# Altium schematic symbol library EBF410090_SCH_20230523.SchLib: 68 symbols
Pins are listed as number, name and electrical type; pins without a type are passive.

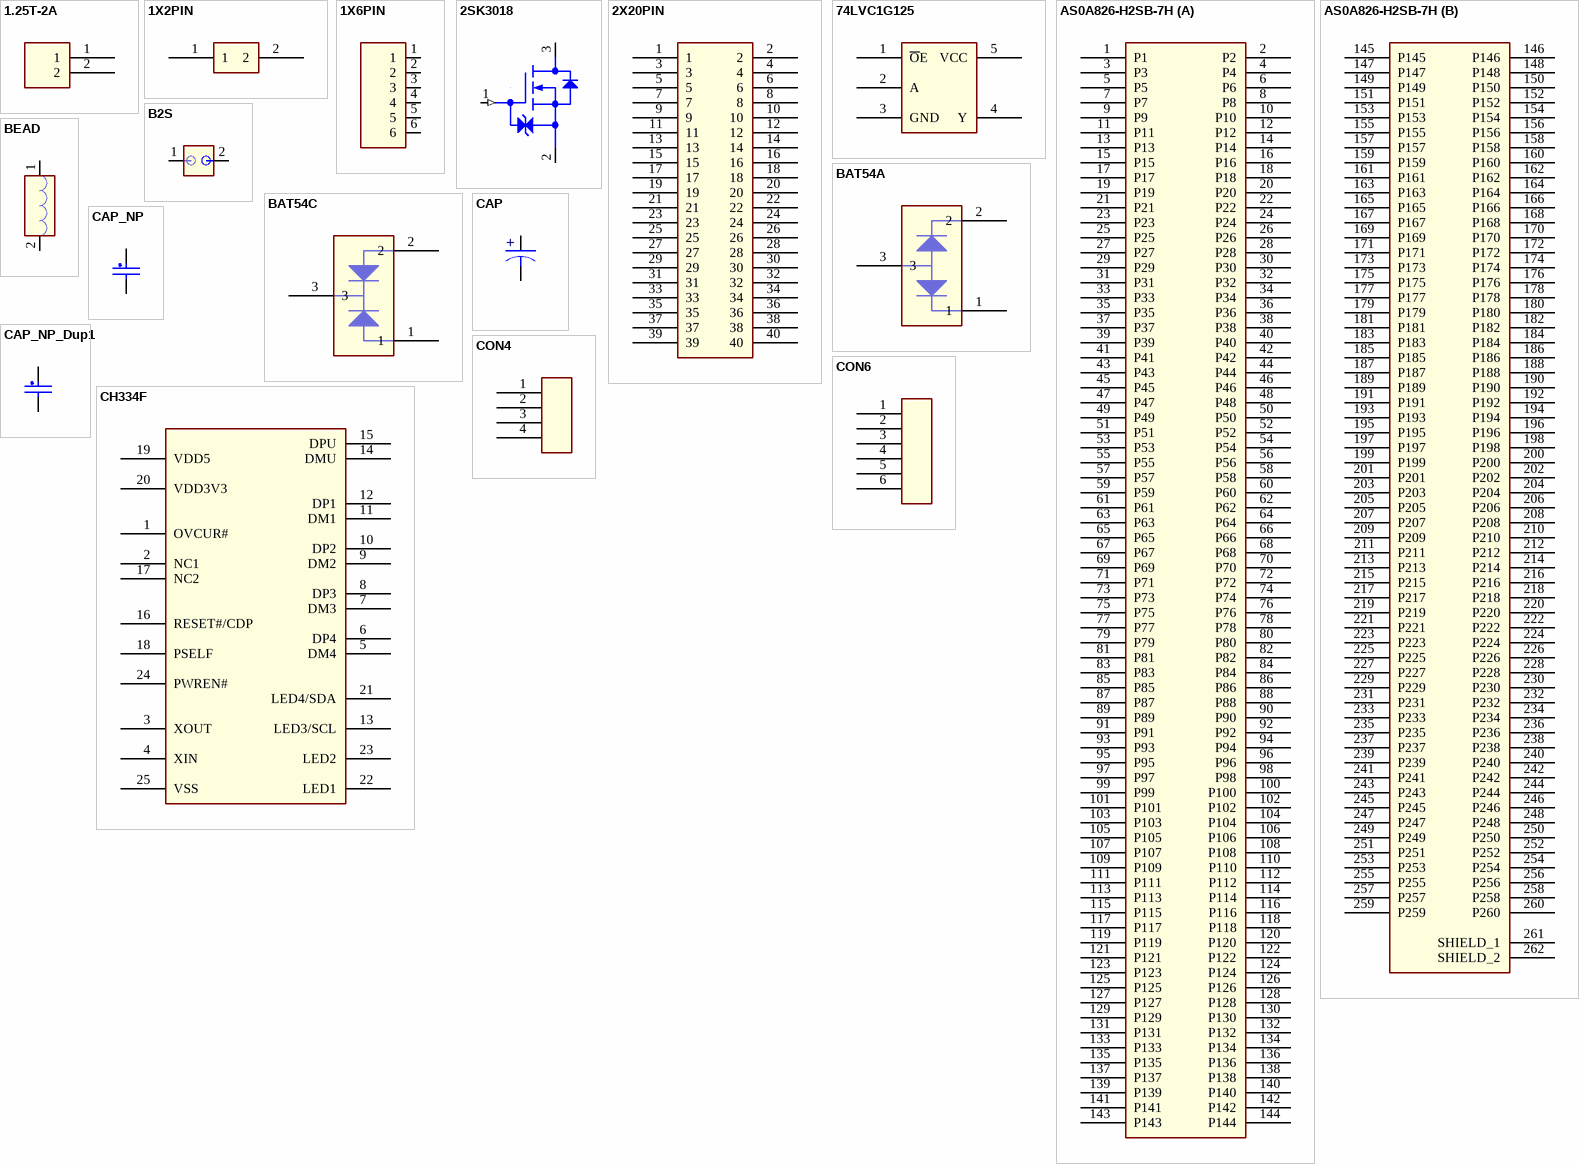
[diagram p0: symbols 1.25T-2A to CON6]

## 1.25T-2A
designator J?
footprint gh1p25_th_2p
pins: 1, 2

## 1X2PIN
designator J?
pins: 1, 2

## 1X6PIN
designator J?
pins: 1, 2, 3, 4, 5, 6

## 2SK3018
designator Q?
CLASS: IC
pins: 1 GATE (in), 2 SOURCE, 3 DRAIN

## 2X20PIN
designator J?
pins: 1, 2, 3, 4, 5, 6, 7, 8, 9, 10, 11, 12, 13, 14, 15, 16, 17, 18, 19, 20, 21, 22, 23, 24, 25, 26, 27, 28, 29, 30, 31, 32, 33, 34, 35, 36, 37, 38, 39, 40

## 74LVC1G125
designator U?
footprint SOT-353
pins: 1 ~{O}E, 2 A, 3 GND, 4 Y, 5 VCC

## AS0A826-H2SB-7H
designator J?
part A pins: 1 P1, 2 P2, 3 P3, 4 P4, 5 P5, 6 P6, 7 P7, 8 P8, 9 P9, 10 P10, 11 P11, 12 P12, 13 P13, 14 P14, 15 P15, 16 P16, 17 P17, 18 P18, 19 P19, 20 P20, 21 P21, 22 P22, 23 P23, 24 P24, 25 P25, 26 P26, 27 P27, 28 P28, 29 P29, 30 P30, 31 P31, 32 P32, 33 P33, 34 P34, 35 P35, 36 P36, 37 P37, 38 P38, 39 P39, 40 P40, 41 P41, 42 P42, 43 P43, 44 P44, 45 P45, 46 P46, 47 P47, 48 P48, 49 P49, 50 P50, 51 P51, 52 P52, 53 P53, 54 P54, 55 P55, 56 P56, 57 P57, 58 P58, 59 P59, 60 P60, 61 P61, 62 P62, 63 P63, 64 P64, 65 P65, 66 P66, 67 P67, 68 P68, 69 P69, 70 P70, 71 P71, 72 P72, 73 P73, 74 P74, 75 P75, 76 P76, 77 P77, 78 P78, 79 P79, 80 P80, 81 P81, 82 P82, 83 P83, 84 P84, 85 P85, 86 P86, 87 P87, 88 P88, 89 P89, 90 P90, 91 P91, 92 P92, 93 P93, 94 P94, 95 P95, 96 P96, 97 P97, 98 P98, 99 P99, 100 P100, 101 P101, 102 P102, 103 P103, 104 P104, 105 P105, 106 P106, 107 P107, 108 P108, 109 P109, 110 P110, 111 P111, 112 P112, 113 P113, 114 P114, 115 P115, 116 P116, 117 P117, 118 P118, 119 P119, 120 P120, 121 P121, 122 P122, 123 P123, 124 P124, 125 P125, 126 P126, 127 P127, 128 P128, 129 P129, 130 P130, 131 P131, 132 P132, 133 P133, 134 P134, 135 P135, 136 P136, 137 P137, 138 P138, 139 P139, 140 P140, 141 P141, 142 P142, 143 P143, 144 P144
part B pins: 145 P145, 146 P146, 147 P147, 148 P148, 149 P149, 150 P150, 151 P151, 152 P152, 153 P153, 154 P154, 155 P155, 156 P156, 157 P157, 158 P158, 159 P159, 160 P160, 161 P161, 162 P162, 163 P163, 164 P164, 165 P165, 166 P166, 167 P167, 168 P168, 169 P169, 170 P170, 171 P171, 172 P172, 173 P173, 174 P174, 175 P175, 176 P176, 177 P177, 178 P178, 179 P179, 180 P180, 181 P181, 182 P182, 183 P183, 184 P184, 185 P185, 186 P186, 187 P187, 188 P188, 189 P189, 190 P190, 191 P191, 192 P192, 193 P193, 194 P194, 195 P195, 196 P196, 197 P197, 198 P198, 199 P199, 200 P200, 201 P201, 202 P202, 203 P203, 204 P204, 205 P205, 206 P206, 207 P207, 208 P208, 209 P209, 210 P210, 211 P211, 212 P212, 213 P213, 214 P214, 215 P215, 216 P216, 217 P217, 218 P218, 219 P219, 220 P220, 221 P221, 222 P222, 223 P223, 224 P224, 225 P225, 226 P226, 227 P227, 228 P228, 229 P229, 230 P230, 231 P231, 232 P232, 233 P233, 234 P234, 235 P235, 236 P236, 237 P237, 238 P238, 239 P239, 240 P240, 241 P241, 242 P242, 243 P243, 244 P244, 245 P245, 246 P246, 247 P247, 248 P248, 249 P249, 250 P250, 251 P251, 252 P252, 253 P253, 254 P254, 255 P255, 256 P256, 257 P257, 258 P258, 259 P259, 260 P260, 261 SHIELD_1, 262 SHIELD_2

## B2S
designator J?
pins: 1, 2

## BAT54A
designator D?
footprint SOT23
pins: 1, 2, 3

## BAT54C
designator D?
footprint SOT23
pins: 1, 2, 3

## BEAD
designator L?
CLASS: DISCRETE
pins: 1, 2

## CAP
designator C?
footprint T2012
pins: 1, 2

## CAP_NP
designator C?
CLASS: DISCRETE
pins: 1, 2

## CAP_NP_Dup1
designator C?
CLASS: DISCRETE
pins: 1, 2

## CH334F
designator U?
pins: 1 OVCUR#, 2 NC1, 3 XOUT, 4 XIN, 5 DM4, 6 DP4, 7 DM3, 8 DP3, 9 DM2, 10 DP2, 11 DM1, 12 DP1, 13 LED3/SCL, 14 DMU, 15 DPU, 16 RESET#/CDP, 17 NC2, 18 PSELF, 19 VDD5, 20 VDD3V3, 21 LED4/SDA, 22 LED1, 23 LED2, 24 PWREN#, 25 VSS

## CON4
designator J?
pins: 1, 2, 3, 4

## CON6
designator J?
pins: 1, 2, 3, 4, 5, 6

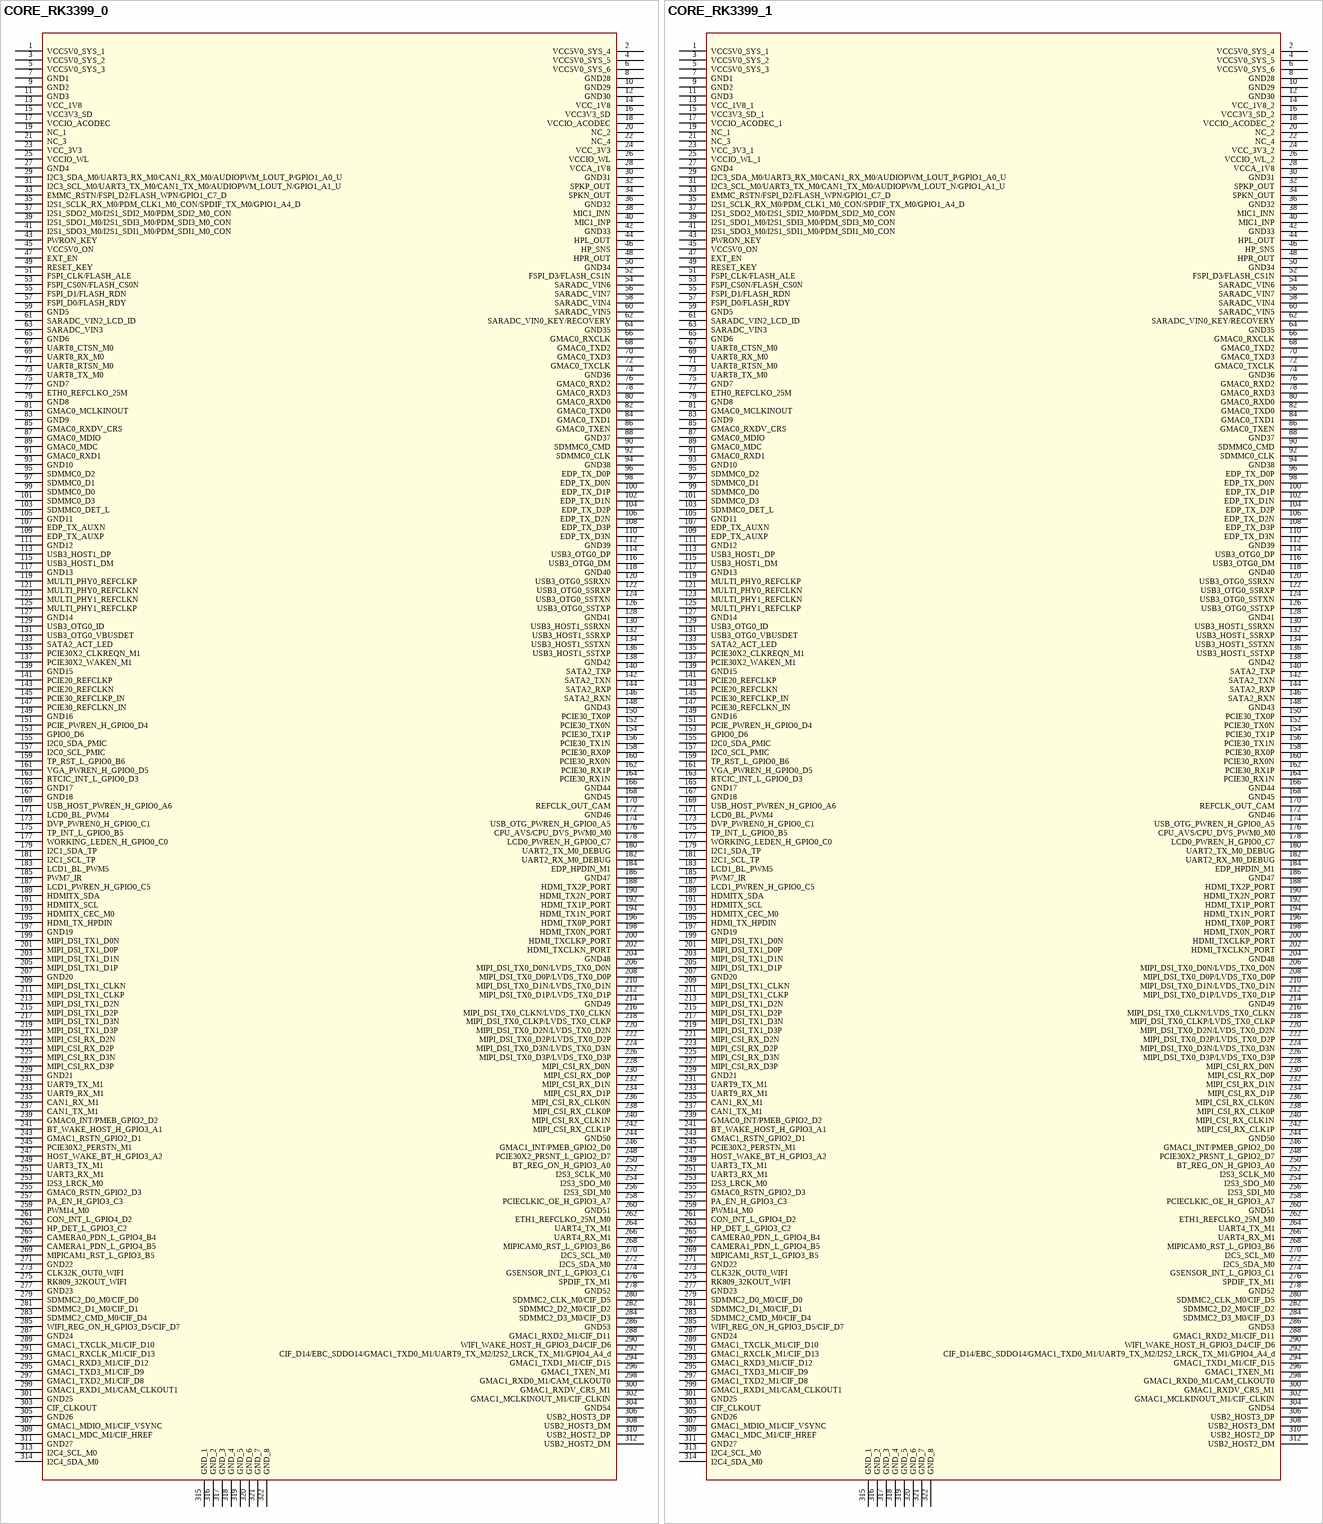
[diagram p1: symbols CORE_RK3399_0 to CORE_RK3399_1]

## CORE_RK3399_0
designator U?
pins: 1 VCC5V0_SYS_1, 2 VCC5V0_SYS_4, 3 VCC5V0_SYS_2, 4 VCC5V0_SYS_5, 5 VCC5V0_SYS_3, 6 VCC5V0_SYS_6, 7 GND1, 8 GND28, 9 GND2, 10 GND29, 11 GND3, 12 GND30, 13 VCC_1V8, 14 VCC_1V8, 15 VCC3V3_SD, 16 VCC3V3_SD, 17 VCCIO_ACODEC, 18 VCCIO_ACODEC, 19 NC_1, 20 NC_2, 21 NC_3, 22 NC_4, 23 VCC_3V3, 24 VCC_3V3, 25 VCCIO_WL, 26 VCCIO_WL, 27 GND4, 28 VCCA_1V8, 29 I2C3_SDA_M0/UART3_RX_M0/CAN1_RX_M0/AUDIOPWM_LOUT_P/GPIO1_A0_U, 30 GND31, 31 I2C3_SCL_M0/UART3_TX_M0/CAN1_TX_M0/AUDIOPWM_LOUT_N/GPIO1_A1_U, 32 SPKP_OUT, 33 EMMC_RSTN/FSPI_D2/FLASH_WPN/GPIO1_C7_D, 34 SPKN_OUT, 35 I2S1_SCLK_RX_M0/PDM_CLK1_M0_CON/SPDIF_TX_M0/GPIO1_A4_D, 36 GND32, 37 I2S1_SDO2_M0/I2S1_SDI2_M0/PDM_SDI2_M0_CON, 38 MIC1_INN, 39 I2S1_SDO1_M0/I2S1_SDI3_M0/PDM_SDI3_M0_CON, 40 MIC1_INP, 41 I2S1_SDO3_M0/I2S1_SDI1_M0/PDM_SDI1_M0_CON, 42 GND33, 43 PWRON_KEY, 44 HPL_OUT, 45 VCC5V0_ON, 46 HP_SNS, 47 EXT_EN, 48 HPR_OUT, 49 RESET_KEY, 50 GND34, 51 FSPI_CLK/FLASH_ALE, 52 FSPI_D3/FLASH_CS1N, 53 FSPI_CS0N/FLASH_CS0N, 54 SARADC_VIN6, 55 FSPI_D1/FLASH_RDN, 56 SARADC_VIN7, 57 FSPI_D0/FLASH_RDY, 58 SARADC_VIN4, 59 GND5, 60 SARADC_VIN5, 61 SARADC_VIN2_LCD_ID, 62 SARADC_VIN0_KEY/RECOVERY, 63 SARADC_VIN3, 64 GND35, 65 GND6, 66 GMAC0_RXCLK, 67 UART8_CTSN_M0, 68 GMAC0_TXD2, 69 UART8_RX_M0, 70 GMAC0_TXD3, 71 UART8_RTSN_M0, 72 GMAC0_TXCLK, 73 UART8_TX_M0, 74 GND36, 75 GND7, 76 GMAC0_RXD2, 77 ETH0_REFCLKO_25M, 78 GMAC0_RXD3, 79 GND8, 80 GMAC0_RXD0, 81 GMAC0_MCLKINOUT, 82 GMAC0_TXD0, 83 GND9, 84 GMAC0_TXD1, 85 GMAC0_RXDV_CRS, 86 GMAC0_TXEN, 87 GMAC0_MDIO, 88 GND37, 89 GMAC0_MDC, 90 SDMMC0_CMD, 91 GMAC0_RXD1, 92 SDMMC0_CLK, 93 GND10, 94 GND38, 95 SDMMC0_D2, 96 EDP_TX_D0P, 97 SDMMC0_D1, 98 EDP_TX_D0N, 99 SDMMC0_D0, 100 EDP_TX_D1P, 101 SDMMC0_D3, 102 EDP_TX_D1N, 103 SDMMC0_DET_L, 104 EDP_TX_D2P, 105 GND11, 106 EDP_TX_D2N, 107 EDP_TX_AUXN, 108 EDP_TX_D3P, 109 EDP_TX_AUXP, 110 EDP_TX_D3N, 111 GND12, 112 GND39, 113 USB3_HOST1_DP, 114 USB3_OTG0_DP, 115 USB3_HOST1_DM, 116 USB3_OTG0_DM, 117 GND13, 118 GND40, 119 MULTI_PHY0_REFCLKP, 120 USB3_OTG0_SSRXN, 121 MULTI_PHY0_REFCLKN, 122 USB3_OTG0_SSRXP, 123 MULTI_PHY1_REFCLKN, 124 USB3_OTG0_SSTXN, 125 MULTI_PHY1_REFCLKP, 126 USB3_OTG0_SSTXP, 127 GND14, 128 GND41, 129 USB3_OTG0_ID, 130 USB3_HOST1_SSRXN, 131 USB3_OTG0_VBUSDET, 132 USB3_HOST1_SSRXP, 133 SATA2_ACT_LED, 134 USB3_HOST1_SSTXN, 135 PCIE30X2_CLKREQN_M1, 136 USB3_HOST1_SSTXP, 137 PCIE30X2_WAKEN_M1, 138 GND42, 139 GND15, 140 SATA2_TXP, 141 PCIE20_REFCLKP, 142 SATA2_TXN, 143 PCIE20_REFCLKN, 144 SATA2_RXP, 145 PCIE30_REFCLKP_IN, 146 SATA2_RXN, 147 PCIE30_REFCLKN_IN, 148 GND43, 149 GND16, 150 PCIE30_TX0P, 151 PCIE_PWREN_H_GPIO0_D4, 152 PCIE30_TX0N, 153 GPIO0_D6, 154 PCIE30_TX1P, 155 I2C0_SDA_PMIC, 156 PCIE30_TX1N, 157 I2C0_SCL_PMIC, 158 PCIE30_RX0P, 159 TP_RST_L_GPIO0_B6, 160 PCIE30_RX0N, 161 VGA_PWREN_H_GPIO0_D5, 162 PCIE30_RX1P, 163 RTCIC_INT_L_GPIO0_D3, 164 PCIE30_RX1N, 165 GND17, 166 GND44, 167 GND18, 168 GND45, 169 USB_HOST_PWREN_H_GPIO0_A6, 170 REFCLK_OUT_CAM, 171 LCD0_BL_PWM4, 172 GND46, 173 DVP_PWREN0_H_GPIO0_C1, 174 USB_OTG_PWREN_H_GPIO0_A5, 175 TP_INT_L_GPIO0_B5, 176 CPU_AVS/CPU_DVS_PWM0_M0, 177 WORKING_LEDEN_H_GPIO0_C0, 178 LCD0_PWREN_H_GPIO0_C7, 179 I2C1_SDA_TP, 180 UART2_TX_M0_DEBUG, 181 I2C1_SCL_TP, 182 UART2_RX_M0_DEBUG, 183 LCD1_BL_PWM5, 184 EDP_HPDIN_M1, 185 PWM7_IR, 186 GND47, 187 LCD1_PWREN_H_GPIO0_C5, 188 HDMI_TX2P_PORT, 189 HDMITX_SDA, 190 HDMI_TX2N_PORT, 191 HDMITX_SCL, 192 HDMI_TX1P_PORT, 193 HDMITX_CEC_M0, 194 HDMI_TX1N_PORT, 195 HDMI_TX_HPDIN, 196 HDMI_TX0P_PORT, 197 GND19, 198 HDMI_TX0N_PORT, 199 MIPI_DSI_TX1_D0N, 200 HDMI_TXCLKP_PORT, 201 MIPI_DSI_TX1_D0P, 202 HDMI_TXCLKN_PORT, 203 MIPI_DSI_TX1_D1N, 204 GND48, 205 MIPI_DSI_TX1_D1P, 206 MIPI_DSI_TX0_D0N/LVDS_TX0_D0N, 207 GND20, 208 MIPI_DSI_TX0_D0P/LVDS_TX0_D0P, 209 MIPI_DSI_TX1_CLKN, 210 MIPI_DSI_TX0_D1N/LVDS_TX0_D1N, 211 MIPI_DSI_TX1_CLKP, 212 MIPI_DSI_TX0_D1P/LVDS_TX0_D1P, 213 MIPI_DSI_TX1_D2N, 214 GND49, 215 MIPI_DSI_TX1_D2P, 216 MIPI_DSI_TX0_CLKN/LVDS_TX0_CLKN, 217 MIPI_DSI_TX1_D3N, 218 MIPI_DSI_TX0_CLKP/LVDS_TX0_CLKP, 219 MIPI_DSI_TX1_D3P, 220 MIPI_DSI_TX0_D2N/LVDS_TX0_D2N, 221 MIPI_CSI_RX_D2N, 222 MIPI_DSI_TX0_D2P/LVDS_TX0_D2P, 223 MIPI_CSI_RX_D2P, 224 MIPI_DSI_TX0_D3N/LVDS_TX0_D3N, 225 MIPI_CSI_RX_D3N, 226 MIPI_DSI_TX0_D3P/LVDS_TX0_D3P, 227 MIPI_CSI_RX_D3P, 228 MIPI_CSI_RX_D0N, 229 GND21, 230 MIPI_CSI_RX_D0P, 231 UART9_TX_M1, 232 MIPI_CSI_RX_D1N, 233 UART9_RX_M1, 234 MIPI_CSI_RX_D1P, 235 CAN1_RX_M1, 236 MIPI_CSI_RX_CLK0N, 237 CAN1_TX_M1, 238 MIPI_CSI_RX_CLK0P, 239 GMAC0_INT/PMEB_GPIO2_D2, 240 MIPI_CSI_RX_CLK1N, 241 BT_WAKE_HOST_H_GPIO3_A1, 242 MIPI_CSI_RX_CLK1P, 243 GMAC1_RSTN_GPIO2_D1, 244 GND50, 245 PCIE30X2_PERSTN_M1, 246 GMAC1_INT/PMEB_GPIO2_D0, 247 HOST_WAKE_BT_H_GPIO3_A2, 248 PCIE30X2_PRSNT_L_GPIO2_D7, 249 UART3_TX_M1, 250 BT_REG_ON_H_GPIO3_A0, 251 UART3_RX_M1, 252 I2S3_SCLK_M0, 253 I2S3_LRCK_M0, 254 I2S3_SDO_M0, 255 GMAC0_RSTN_GPIO2_D3, 256 I2S3_SDI_M0, 257 PA_EN_H_GPIO3_C3, 258 PCIECLKIC_OE_H_GPIO3_A7, 259 PWM14_M0, 260 GND51, 261 CON_INT_L_GPIO4_D2, 262 ETH1_REFCLKO_25M_M0, 263 HP_DET_L_GPIO3_C2, 264 UART4_TX_M1, 265 CAMERA0_PDN_L_GPIO4_B4, 266 UART4_RX_M1, 267 CAMERA1_PDN_L_GPIO4_B5, 268 MIPICAM0_RST_L_GPIO3_B6, 269 MIPICAM1_RST_L_GPIO3_B5, 270 I2C5_SCL_M0, 271 GND22, 272 I2C5_SDA_M0, 273 CLK32K_OUT0_WIFI, 274 GSENSOR_INT_L_GPIO3_C1, 275 RK809_32KOUT_WIFI, 276 SPDIF_TX_M1, 277 GND23, 278 GND52, 279 SDMMC2_D0_M0/CIF_D0, 280 SDMMC2_CLK_M0/CIF_D5, 281 SDMMC2_D1_M0/CIF_D1, 282 SDMMC2_D2_M0/CIF_D2, 283 SDMMC2_CMD_M0/CIF_D4, 284 SDMMC2_D3_M0/CIF_D3, 285 WIFI_REG_ON_H_GPIO3_D5/CIF_D7, 286 GND53, 287 GND24, 288 GMAC1_RXD2_M1/CIF_D11, 289 GMAC1_TXCLK_M1/CIF_D10, 290 WIFI_WAKE_HOST_H_GPIO3_D4/CIF_D6, 291 GMAC1_RXCLK_M1/CIF_D13, 292 CIF_D14/EBC_SDDO14/GMAC1_TXD0_M1/UART9_TX_M2/I2S2_LRCK_TX_M1/GPIO4_A4_d, 293 GMAC1_RXD3_M1/CIF_D12, 294 GMAC1_TXD1_M1/CIF_D15, 295 GMAC1_TXD3_M1/CIF_D9, 296 GMAC1_TXEN_M1, 297 GMAC1_TXD2_M1/CIF_D8, 298 GMAC1_RXD0_M1/CAM_CLKOUT0, 299 GMAC1_RXD1_M1/CAM_CLKOUT1, 300 GMAC1_RXDV_CRS_M1, 301 GND25, 302 GMAC1_MCLKINOUT_M1/CIF_CLKIN, 303 CIF_CLKOUT, 304 GND54, 305 GND26, 306 USB2_HOST3_DP, 307 GMAC1_MDIO_M1/CIF_VSYNC, 308 USB2_HOST3_DM, 309 GMAC1_MDC_M1/CIF_HREF, 310 USB2_HOST2_DP, 311 GND27, 312 USB2_HOST2_DM, 313 I2C4_SCL_M0, 314 I2C4_SDA_M0, 315 GND_1, 316 GND_2, 317 GND_3, 318 GND_4, 319 GND_5, 320 GND_6, 321 GND_7, 322 GND_8

## CORE_RK3399_1
designator U?
pins: 1 VCC5V0_SYS_1, 2 VCC5V0_SYS_4, 3 VCC5V0_SYS_2, 4 VCC5V0_SYS_5, 5 VCC5V0_SYS_3, 6 VCC5V0_SYS_6, 7 GND1, 8 GND28, 9 GND2, 10 GND29, 11 GND3, 12 GND30, 13 VCC_1V8_1, 14 VCC_1V8_2, 15 VCC3V3_SD_1, 16 VCC3V3_SD_2, 17 VCCIO_ACODEC_1, 18 VCCIO_ACODEC_2, 19 NC_1, 20 NC_2, 21 NC_3, 22 NC_4, 23 VCC_3V3_1, 24 VCC_3V3_2, 25 VCCIO_WL_1, 26 VCCIO_WL_2, 27 GND4, 28 VCCA_1V8, 29 I2C3_SDA_M0/UART3_RX_M0/CAN1_RX_M0/AUDIOPWM_LOUT_P/GPIO1_A0_U, 30 GND31, 31 I2C3_SCL_M0/UART3_TX_M0/CAN1_TX_M0/AUDIOPWM_LOUT_N/GPIO1_A1_U, 32 SPKP_OUT, 33 EMMC_RSTN/FSPI_D2/FLASH_WPN/GPIO1_C7_D, 34 SPKN_OUT, 35 I2S1_SCLK_RX_M0/PDM_CLK1_M0_CON/SPDIF_TX_M0/GPIO1_A4_D, 36 GND32, 37 I2S1_SDO2_M0/I2S1_SDI2_M0/PDM_SDI2_M0_CON, 38 MIC1_INN, 39 I2S1_SDO1_M0/I2S1_SDI3_M0/PDM_SDI3_M0_CON, 40 MIC1_INP, 41 I2S1_SDO3_M0/I2S1_SDI1_M0/PDM_SDI1_M0_CON, 42 GND33, 43 PWRON_KEY, 44 HPL_OUT, 45 VCC5V0_ON, 46 HP_SNS, 47 EXT_EN, 48 HPR_OUT, 49 RESET_KEY, 50 GND34, 51 FSPI_CLK/FLASH_ALE, 52 FSPI_D3/FLASH_CS1N, 53 FSPI_CS0N/FLASH_CS0N, 54 SARADC_VIN6, 55 FSPI_D1/FLASH_RDN, 56 SARADC_VIN7, 57 FSPI_D0/FLASH_RDY, 58 SARADC_VIN4, 59 GND5, 60 SARADC_VIN5, 61 SARADC_VIN2_LCD_ID, 62 SARADC_VIN0_KEY/RECOVERY, 63 SARADC_VIN3, 64 GND35, 65 GND6, 66 GMAC0_RXCLK, 67 UART8_CTSN_M0, 68 GMAC0_TXD2, 69 UART8_RX_M0, 70 GMAC0_TXD3, 71 UART8_RTSN_M0, 72 GMAC0_TXCLK, 73 UART8_TX_M0, 74 GND36, 75 GND7, 76 GMAC0_RXD2, 77 ETH0_REFCLKO_25M, 78 GMAC0_RXD3, 79 GND8, 80 GMAC0_RXD0, 81 GMAC0_MCLKINOUT, 82 GMAC0_TXD0, 83 GND9, 84 GMAC0_TXD1, 85 GMAC0_RXDV_CRS, 86 GMAC0_TXEN, 87 GMAC0_MDIO, 88 GND37, 89 GMAC0_MDC, 90 SDMMC0_CMD, 91 GMAC0_RXD1, 92 SDMMC0_CLK, 93 GND10, 94 GND38, 95 SDMMC0_D2, 96 EDP_TX_D0P, 97 SDMMC0_D1, 98 EDP_TX_D0N, 99 SDMMC0_D0, 100 EDP_TX_D1P, 101 SDMMC0_D3, 102 EDP_TX_D1N, 103 SDMMC0_DET_L, 104 EDP_TX_D2P, 105 GND11, 106 EDP_TX_D2N, 107 EDP_TX_AUXN, 108 EDP_TX_D3P, 109 EDP_TX_AUXP, 110 EDP_TX_D3N, 111 GND12, 112 GND39, 113 USB3_HOST1_DP, 114 USB3_OTG0_DP, 115 USB3_HOST1_DM, 116 USB3_OTG0_DM, 117 GND13, 118 GND40, 119 MULTI_PHY0_REFCLKP, 120 USB3_OTG0_SSRXN, 121 MULTI_PHY0_REFCLKN, 122 USB3_OTG0_SSRXP, 123 MULTI_PHY1_REFCLKN, 124 USB3_OTG0_SSTXN, 125 MULTI_PHY1_REFCLKP, 126 USB3_OTG0_SSTXP, 127 GND14, 128 GND41, 129 USB3_OTG0_ID, 130 USB3_HOST1_SSRXN, 131 USB3_OTG0_VBUSDET, 132 USB3_HOST1_SSRXP, 133 SATA2_ACT_LED, 134 USB3_HOST1_SSTXN, 135 PCIE30X2_CLKREQN_M1, 136 USB3_HOST1_SSTXP, 137 PCIE30X2_WAKEN_M1, 138 GND42, 139 GND15, 140 SATA2_TXP, 141 PCIE20_REFCLKP, 142 SATA2_TXN, 143 PCIE20_REFCLKN, 144 SATA2_RXP, 145 PCIE30_REFCLKP_IN, 146 SATA2_RXN, 147 PCIE30_REFCLKN_IN, 148 GND43, 149 GND16, 150 PCIE30_TX0P, 151 PCIE_PWREN_H_GPIO0_D4, 152 PCIE30_TX0N, 153 GPIO0_D6, 154 PCIE30_TX1P, 155 I2C0_SDA_PMIC, 156 PCIE30_TX1N, 157 I2C0_SCL_PMIC, 158 PCIE30_RX0P, 159 TP_RST_L_GPIO0_B6, 160 PCIE30_RX0N, 161 VGA_PWREN_H_GPIO0_D5, 162 PCIE30_RX1P, 163 RTCIC_INT_L_GPIO0_D3, 164 PCIE30_RX1N, 165 GND17, 166 GND44, 167 GND18, 168 GND45, 169 USB_HOST_PWREN_H_GPIO0_A6, 170 REFCLK_OUT_CAM, 171 LCD0_BL_PWM4, 172 GND46, 173 DVP_PWREN0_H_GPIO0_C1, 174 USB_OTG_PWREN_H_GPIO0_A5, 175 TP_INT_L_GPIO0_B5, 176 CPU_AVS/CPU_DVS_PWM0_M0, 177 WORKING_LEDEN_H_GPIO0_C0, 178 LCD0_PWREN_H_GPIO0_C7, 179 I2C1_SDA_TP, 180 UART2_TX_M0_DEBUG, 181 I2C1_SCL_TP, 182 UART2_RX_M0_DEBUG, 183 LCD1_BL_PWM5, 184 EDP_HPDIN_M1, 185 PWM7_IR, 186 GND47, 187 LCD1_PWREN_H_GPIO0_C5, 188 HDMI_TX2P_PORT, 189 HDMITX_SDA, 190 HDMI_TX2N_PORT, 191 HDMITX_SCL, 192 HDMI_TX1P_PORT, 193 HDMITX_CEC_M0, 194 HDMI_TX1N_PORT, 195 HDMI_TX_HPDIN, 196 HDMI_TX0P_PORT, 197 GND19, 198 HDMI_TX0N_PORT, 199 MIPI_DSI_TX1_D0N, 200 HDMI_TXCLKP_PORT, 201 MIPI_DSI_TX1_D0P, 202 HDMI_TXCLKN_PORT, 203 MIPI_DSI_TX1_D1N, 204 GND48, 205 MIPI_DSI_TX1_D1P, 206 MIPI_DSI_TX0_D0N/LVDS_TX0_D0N, 207 GND20, 208 MIPI_DSI_TX0_D0P/LVDS_TX0_D0P, 209 MIPI_DSI_TX1_CLKN, 210 MIPI_DSI_TX0_D1N/LVDS_TX0_D1N, 211 MIPI_DSI_TX1_CLKP, 212 MIPI_DSI_TX0_D1P/LVDS_TX0_D1P, 213 MIPI_DSI_TX1_D2N, 214 GND49, 215 MIPI_DSI_TX1_D2P, 216 MIPI_DSI_TX0_CLKN/LVDS_TX0_CLKN, 217 MIPI_DSI_TX1_D3N, 218 MIPI_DSI_TX0_CLKP/LVDS_TX0_CLKP, 219 MIPI_DSI_TX1_D3P, 220 MIPI_DSI_TX0_D2N/LVDS_TX0_D2N, 221 MIPI_CSI_RX_D2N, 222 MIPI_DSI_TX0_D2P/LVDS_TX0_D2P, 223 MIPI_CSI_RX_D2P, 224 MIPI_DSI_TX0_D3N/LVDS_TX0_D3N, 225 MIPI_CSI_RX_D3N, 226 MIPI_DSI_TX0_D3P/LVDS_TX0_D3P, 227 MIPI_CSI_RX_D3P, 228 MIPI_CSI_RX_D0N, 229 GND21, 230 MIPI_CSI_RX_D0P, 231 UART9_TX_M1, 232 MIPI_CSI_RX_D1N, 233 UART9_RX_M1, 234 MIPI_CSI_RX_D1P, 235 CAN1_RX_M1, 236 MIPI_CSI_RX_CLK0N, 237 CAN1_TX_M1, 238 MIPI_CSI_RX_CLK0P, 239 GMAC0_INT/PMEB_GPIO2_D2, 240 MIPI_CSI_RX_CLK1N, 241 BT_WAKE_HOST_H_GPIO3_A1, 242 MIPI_CSI_RX_CLK1P, 243 GMAC1_RSTN_GPIO2_D1, 244 GND50, 245 PCIE30X2_PERSTN_M1, 246 GMAC1_INT/PMEB_GPIO2_D0, 247 HOST_WAKE_BT_H_GPIO3_A2, 248 PCIE30X2_PRSNT_L_GPIO2_D7, 249 UART3_TX_M1, 250 BT_REG_ON_H_GPIO3_A0, 251 UART3_RX_M1, 252 I2S3_SCLK_M0, 253 I2S3_LRCK_M0, 254 I2S3_SDO_M0, 255 GMAC0_RSTN_GPIO2_D3, 256 I2S3_SDI_M0, 257 PA_EN_H_GPIO3_C3, 258 PCIECLKIC_OE_H_GPIO3_A7, 259 PWM14_M0, 260 GND51, 261 CON_INT_L_GPIO4_D2, 262 ETH1_REFCLKO_25M_M0, 263 HP_DET_L_GPIO3_C2, 264 UART4_TX_M1, 265 CAMERA0_PDN_L_GPIO4_B4, 266 UART4_RX_M1, 267 CAMERA1_PDN_L_GPIO4_B5, 268 MIPICAM0_RST_L_GPIO3_B6, 269 MIPICAM1_RST_L_GPIO3_B5, 270 I2C5_SCL_M0, 271 GND22, 272 I2C5_SDA_M0, 273 CLK32K_OUT0_WIFI, 274 GSENSOR_INT_L_GPIO3_C1, 275 RK809_32KOUT_WIFI, 276 SPDIF_TX_M1, 277 GND23, 278 GND52, 279 SDMMC2_D0_M0/CIF_D0, 280 SDMMC2_CLK_M0/CIF_D5, 281 SDMMC2_D1_M0/CIF_D1, 282 SDMMC2_D2_M0/CIF_D2, 283 SDMMC2_CMD_M0/CIF_D4, 284 SDMMC2_D3_M0/CIF_D3, 285 WIFI_REG_ON_H_GPIO3_D5/CIF_D7, 286 GND53, 287 GND24, 288 GMAC1_RXD2_M1/CIF_D11, 289 GMAC1_TXCLK_M1/CIF_D10, 290 WIFI_WAKE_HOST_H_GPIO3_D4/CIF_D6, 291 GMAC1_RXCLK_M1/CIF_D13, 292 CIF_D14/EBC_SDDO14/GMAC1_TXD0_M1/UART9_TX_M2/I2S2_LRCK_TX_M1/GPIO4_A4_d, 293 GMAC1_RXD3_M1/CIF_D12, 294 GMAC1_TXD1_M1/CIF_D15, 295 GMAC1_TXD3_M1/CIF_D9, 296 GMAC1_TXEN_M1, 297 GMAC1_TXD2_M1/CIF_D8, 298 GMAC1_RXD0_M1/CAM_CLKOUT0, 299 GMAC1_RXD1_M1/CAM_CLKOUT1, 300 GMAC1_RXDV_CRS_M1, 301 GND25, 302 GMAC1_MCLKINOUT_M1/CIF_CLKIN, 303 CIF_CLKOUT, 304 GND54, 305 GND26, 306 USB2_HOST3_DP, 307 GMAC1_MDIO_M1/CIF_VSYNC, 308 USB2_HOST3_DM, 309 GMAC1_MDC_M1/CIF_HREF, 310 USB2_HOST2_DP, 311 GND27, 312 USB2_HOST2_DM, 313 I2C4_SCL_M0, 314 I2C4_SDA_M0, 315 GND_1, 316 GND_2, 317 GND_3, 318 GND_4, 319 GND_5, 320 GND_6, 321 GND_7, 322 GND_8

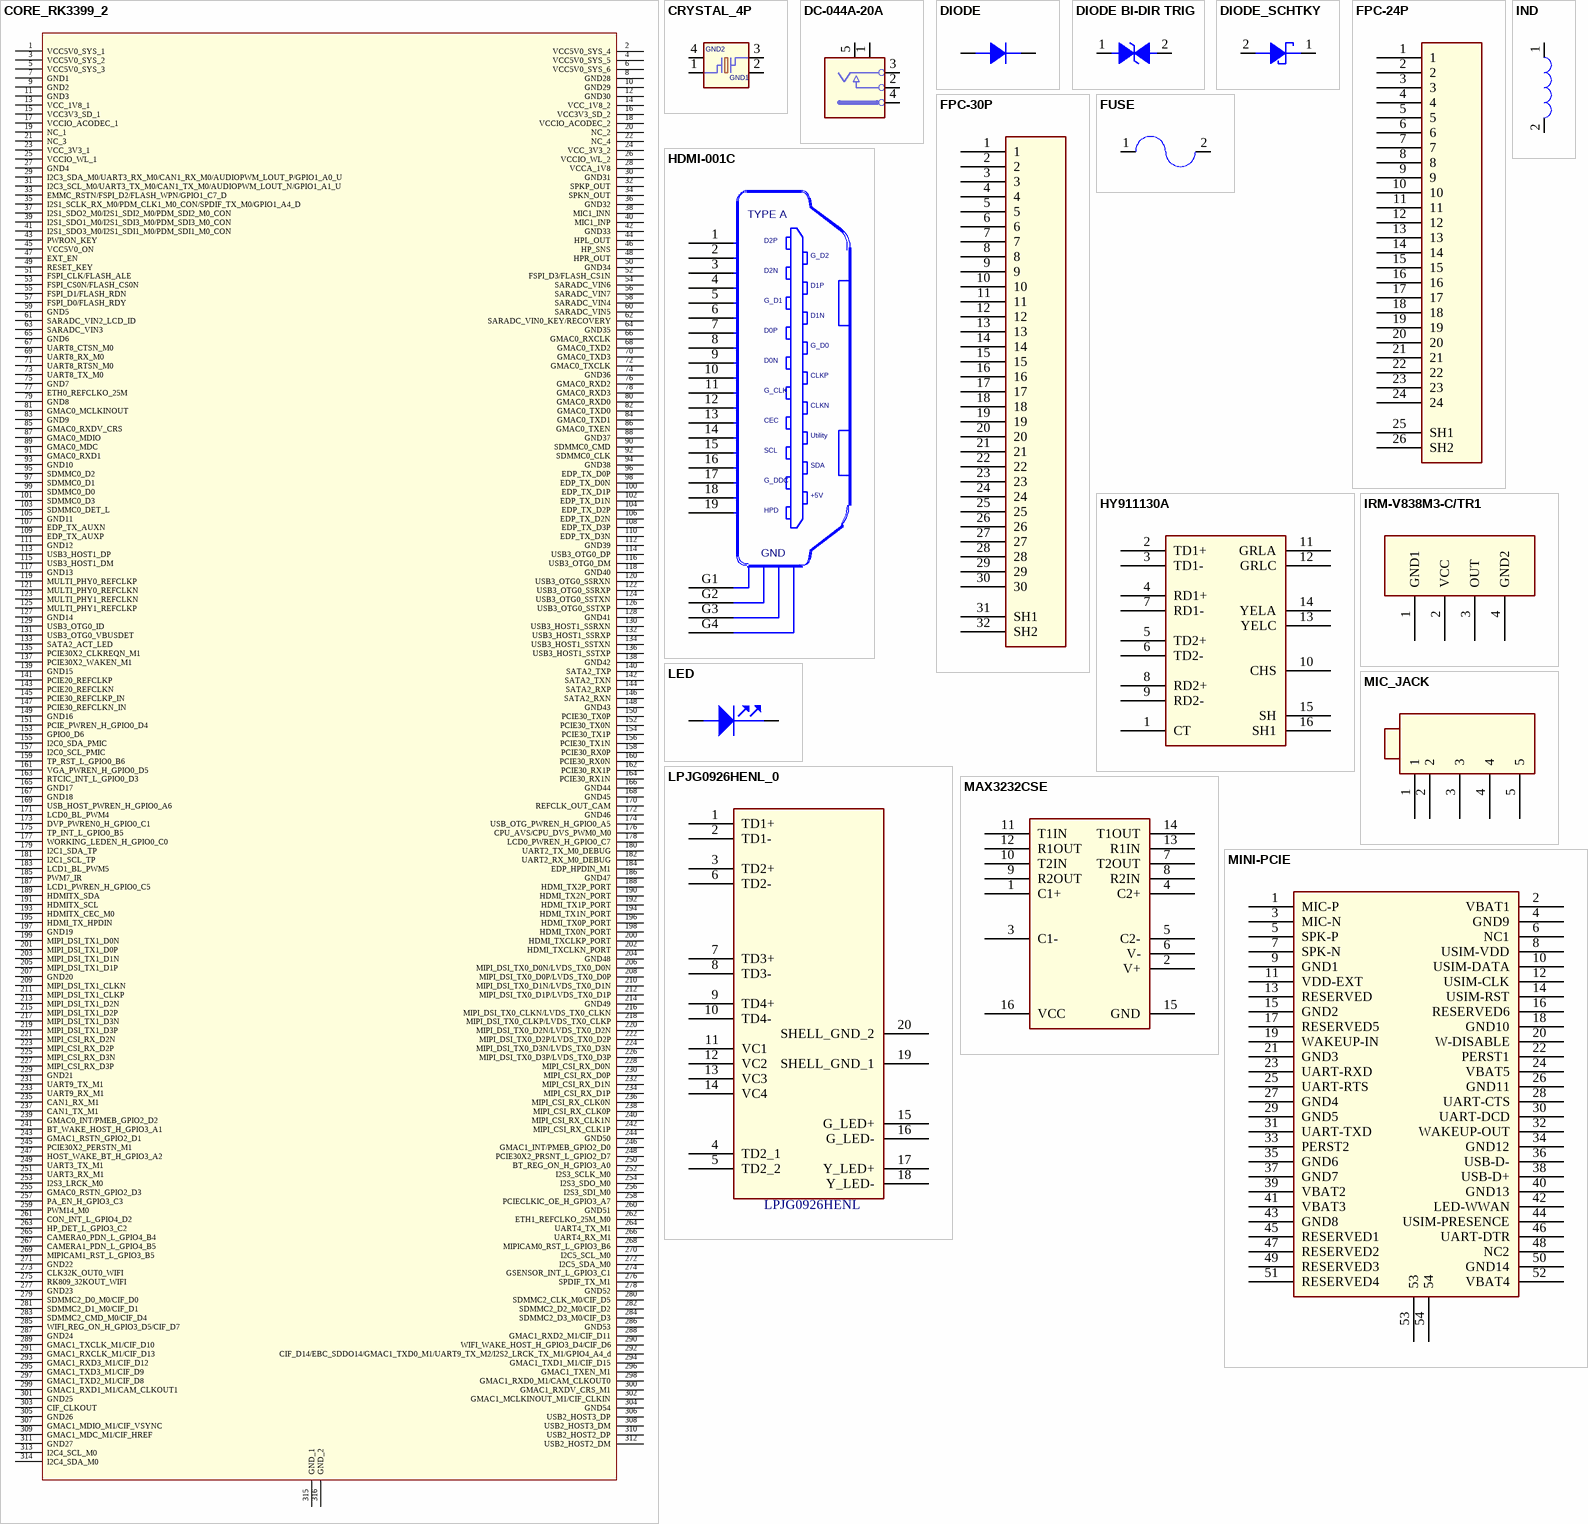
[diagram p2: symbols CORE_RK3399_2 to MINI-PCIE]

## CORE_RK3399_2
designator U?
pins: 1 VCC5V0_SYS_1, 2 VCC5V0_SYS_4, 3 VCC5V0_SYS_2, 4 VCC5V0_SYS_5, 5 VCC5V0_SYS_3, 6 VCC5V0_SYS_6, 7 GND1, 8 GND28, 9 GND2, 10 GND29, 11 GND3, 12 GND30, 13 VCC_1V8_1, 14 VCC_1V8_2, 15 VCC3V3_SD_1, 16 VCC3V3_SD_2, 17 VCCIO_ACODEC_1, 18 VCCIO_ACODEC_2, 19 NC_1, 20 NC_2, 21 NC_3, 22 NC_4, 23 VCC_3V3_1, 24 VCC_3V3_2, 25 VCCIO_WL_1, 26 VCCIO_WL_2, 27 GND4, 28 VCCA_1V8, 29 I2C3_SDA_M0/UART3_RX_M0/CAN1_RX_M0/AUDIOPWM_LOUT_P/GPIO1_A0_U, 30 GND31, 31 I2C3_SCL_M0/UART3_TX_M0/CAN1_TX_M0/AUDIOPWM_LOUT_N/GPIO1_A1_U, 32 SPKP_OUT, 33 EMMC_RSTN/FSPI_D2/FLASH_WPN/GPIO1_C7_D, 34 SPKN_OUT, 35 I2S1_SCLK_RX_M0/PDM_CLK1_M0_CON/SPDIF_TX_M0/GPIO1_A4_D, 36 GND32, 37 I2S1_SDO2_M0/I2S1_SDI2_M0/PDM_SDI2_M0_CON, 38 MIC1_INN, 39 I2S1_SDO1_M0/I2S1_SDI3_M0/PDM_SDI3_M0_CON, 40 MIC1_INP, 41 I2S1_SDO3_M0/I2S1_SDI1_M0/PDM_SDI1_M0_CON, 42 GND33, 43 PWRON_KEY, 44 HPL_OUT, 45 VCC5V0_ON, 46 HP_SNS, 47 EXT_EN, 48 HPR_OUT, 49 RESET_KEY, 50 GND34, 51 FSPI_CLK/FLASH_ALE, 52 FSPI_D3/FLASH_CS1N, 53 FSPI_CS0N/FLASH_CS0N, 54 SARADC_VIN6, 55 FSPI_D1/FLASH_RDN, 56 SARADC_VIN7, 57 FSPI_D0/FLASH_RDY, 58 SARADC_VIN4, 59 GND5, 60 SARADC_VIN5, 61 SARADC_VIN2_LCD_ID, 62 SARADC_VIN0_KEY/RECOVERY, 63 SARADC_VIN3, 64 GND35, 65 GND6, 66 GMAC0_RXCLK, 67 UART8_CTSN_M0, 68 GMAC0_TXD2, 69 UART8_RX_M0, 70 GMAC0_TXD3, 71 UART8_RTSN_M0, 72 GMAC0_TXCLK, 73 UART8_TX_M0, 74 GND36, 75 GND7, 76 GMAC0_RXD2, 77 ETH0_REFCLKO_25M, 78 GMAC0_RXD3, 79 GND8, 80 GMAC0_RXD0, 81 GMAC0_MCLKINOUT, 82 GMAC0_TXD0, 83 GND9, 84 GMAC0_TXD1, 85 GMAC0_RXDV_CRS, 86 GMAC0_TXEN, 87 GMAC0_MDIO, 88 GND37, 89 GMAC0_MDC, 90 SDMMC0_CMD, 91 GMAC0_RXD1, 92 SDMMC0_CLK, 93 GND10, 94 GND38, 95 SDMMC0_D2, 96 EDP_TX_D0P, 97 SDMMC0_D1, 98 EDP_TX_D0N, 99 SDMMC0_D0, 100 EDP_TX_D1P, 101 SDMMC0_D3, 102 EDP_TX_D1N, 103 SDMMC0_DET_L, 104 EDP_TX_D2P, 105 GND11, 106 EDP_TX_D2N, 107 EDP_TX_AUXN, 108 EDP_TX_D3P, 109 EDP_TX_AUXP, 110 EDP_TX_D3N, 111 GND12, 112 GND39, 113 USB3_HOST1_DP, 114 USB3_OTG0_DP, 115 USB3_HOST1_DM, 116 USB3_OTG0_DM, 117 GND13, 118 GND40, 119 MULTI_PHY0_REFCLKP, 120 USB3_OTG0_SSRXN, 121 MULTI_PHY0_REFCLKN, 122 USB3_OTG0_SSRXP, 123 MULTI_PHY1_REFCLKN, 124 USB3_OTG0_SSTXN, 125 MULTI_PHY1_REFCLKP, 126 USB3_OTG0_SSTXP, 127 GND14, 128 GND41, 129 USB3_OTG0_ID, 130 USB3_HOST1_SSRXN, 131 USB3_OTG0_VBUSDET, 132 USB3_HOST1_SSRXP, 133 SATA2_ACT_LED, 134 USB3_HOST1_SSTXN, 135 PCIE30X2_CLKREQN_M1, 136 USB3_HOST1_SSTXP, 137 PCIE30X2_WAKEN_M1, 138 GND42, 139 GND15, 140 SATA2_TXP, 141 PCIE20_REFCLKP, 142 SATA2_TXN, 143 PCIE20_REFCLKN, 144 SATA2_RXP, 145 PCIE30_REFCLKP_IN, 146 SATA2_RXN, 147 PCIE30_REFCLKN_IN, 148 GND43, 149 GND16, 150 PCIE30_TX0P, 151 PCIE_PWREN_H_GPIO0_D4, 152 PCIE30_TX0N, 153 GPIO0_D6, 154 PCIE30_TX1P, 155 I2C0_SDA_PMIC, 156 PCIE30_TX1N, 157 I2C0_SCL_PMIC, 158 PCIE30_RX0P, 159 TP_RST_L_GPIO0_B6, 160 PCIE30_RX0N, 161 VGA_PWREN_H_GPIO0_D5, 162 PCIE30_RX1P, 163 RTCIC_INT_L_GPIO0_D3, 164 PCIE30_RX1N, 165 GND17, 166 GND44, 167 GND18, 168 GND45, 169 USB_HOST_PWREN_H_GPIO0_A6, 170 REFCLK_OUT_CAM, 171 LCD0_BL_PWM4, 172 GND46, 173 DVP_PWREN0_H_GPIO0_C1, 174 USB_OTG_PWREN_H_GPIO0_A5, 175 TP_INT_L_GPIO0_B5, 176 CPU_AVS/CPU_DVS_PWM0_M0, 177 WORKING_LEDEN_H_GPIO0_C0, 178 LCD0_PWREN_H_GPIO0_C7, 179 I2C1_SDA_TP, 180 UART2_TX_M0_DEBUG, 181 I2C1_SCL_TP, 182 UART2_RX_M0_DEBUG, 183 LCD1_BL_PWM5, 184 EDP_HPDIN_M1, 185 PWM7_IR, 186 GND47, 187 LCD1_PWREN_H_GPIO0_C5, 188 HDMI_TX2P_PORT, 189 HDMITX_SDA, 190 HDMI_TX2N_PORT, 191 HDMITX_SCL, 192 HDMI_TX1P_PORT, 193 HDMITX_CEC_M0, 194 HDMI_TX1N_PORT, 195 HDMI_TX_HPDIN, 196 HDMI_TX0P_PORT, 197 GND19, 198 HDMI_TX0N_PORT, 199 MIPI_DSI_TX1_D0N, 200 HDMI_TXCLKP_PORT, 201 MIPI_DSI_TX1_D0P, 202 HDMI_TXCLKN_PORT, 203 MIPI_DSI_TX1_D1N, 204 GND48, 205 MIPI_DSI_TX1_D1P, 206 MIPI_DSI_TX0_D0N/LVDS_TX0_D0N, 207 GND20, 208 MIPI_DSI_TX0_D0P/LVDS_TX0_D0P, 209 MIPI_DSI_TX1_CLKN, 210 MIPI_DSI_TX0_D1N/LVDS_TX0_D1N, 211 MIPI_DSI_TX1_CLKP, 212 MIPI_DSI_TX0_D1P/LVDS_TX0_D1P, 213 MIPI_DSI_TX1_D2N, 214 GND49, 215 MIPI_DSI_TX1_D2P, 216 MIPI_DSI_TX0_CLKN/LVDS_TX0_CLKN, 217 MIPI_DSI_TX1_D3N, 218 MIPI_DSI_TX0_CLKP/LVDS_TX0_CLKP, 219 MIPI_DSI_TX1_D3P, 220 MIPI_DSI_TX0_D2N/LVDS_TX0_D2N, 221 MIPI_CSI_RX_D2N, 222 MIPI_DSI_TX0_D2P/LVDS_TX0_D2P, 223 MIPI_CSI_RX_D2P, 224 MIPI_DSI_TX0_D3N/LVDS_TX0_D3N, 225 MIPI_CSI_RX_D3N, 226 MIPI_DSI_TX0_D3P/LVDS_TX0_D3P, 227 MIPI_CSI_RX_D3P, 228 MIPI_CSI_RX_D0N, 229 GND21, 230 MIPI_CSI_RX_D0P, 231 UART9_TX_M1, 232 MIPI_CSI_RX_D1N, 233 UART9_RX_M1, 234 MIPI_CSI_RX_D1P, 235 CAN1_RX_M1, 236 MIPI_CSI_RX_CLK0N, 237 CAN1_TX_M1, 238 MIPI_CSI_RX_CLK0P, 239 GMAC0_INT/PMEB_GPIO2_D2, 240 MIPI_CSI_RX_CLK1N, 241 BT_WAKE_HOST_H_GPIO3_A1, 242 MIPI_CSI_RX_CLK1P, 243 GMAC1_RSTN_GPIO2_D1, 244 GND50, 245 PCIE30X2_PERSTN_M1, 246 GMAC1_INT/PMEB_GPIO2_D0, 247 HOST_WAKE_BT_H_GPIO3_A2, 248 PCIE30X2_PRSNT_L_GPIO2_D7, 249 UART3_TX_M1, 250 BT_REG_ON_H_GPIO3_A0, 251 UART3_RX_M1, 252 I2S3_SCLK_M0, 253 I2S3_LRCK_M0, 254 I2S3_SDO_M0, 255 GMAC0_RSTN_GPIO2_D3, 256 I2S3_SDI_M0, 257 PA_EN_H_GPIO3_C3, 258 PCIECLKIC_OE_H_GPIO3_A7, 259 PWM14_M0, 260 GND51, 261 CON_INT_L_GPIO4_D2, 262 ETH1_REFCLKO_25M_M0, 263 HP_DET_L_GPIO3_C2, 264 UART4_TX_M1, 265 CAMERA0_PDN_L_GPIO4_B4, 266 UART4_RX_M1, 267 CAMERA1_PDN_L_GPIO4_B5, 268 MIPICAM0_RST_L_GPIO3_B6, 269 MIPICAM1_RST_L_GPIO3_B5, 270 I2C5_SCL_M0, 271 GND22, 272 I2C5_SDA_M0, 273 CLK32K_OUT0_WIFI, 274 GSENSOR_INT_L_GPIO3_C1, 275 RK809_32KOUT_WIFI, 276 SPDIF_TX_M1, 277 GND23, 278 GND52, 279 SDMMC2_D0_M0/CIF_D0, 280 SDMMC2_CLK_M0/CIF_D5, 281 SDMMC2_D1_M0/CIF_D1, 282 SDMMC2_D2_M0/CIF_D2, 283 SDMMC2_CMD_M0/CIF_D4, 284 SDMMC2_D3_M0/CIF_D3, 285 WIFI_REG_ON_H_GPIO3_D5/CIF_D7, 286 GND53, 287 GND24, 288 GMAC1_RXD2_M1/CIF_D11, 289 GMAC1_TXCLK_M1/CIF_D10, 290 WIFI_WAKE_HOST_H_GPIO3_D4/CIF_D6, 291 GMAC1_RXCLK_M1/CIF_D13, 292 CIF_D14/EBC_SDDO14/GMAC1_TXD0_M1/UART9_TX_M2/I2S2_LRCK_TX_M1/GPIO4_A4_d, 293 GMAC1_RXD3_M1/CIF_D12, 294 GMAC1_TXD1_M1/CIF_D15, 295 GMAC1_TXD3_M1/CIF_D9, 296 GMAC1_TXEN_M1, 297 GMAC1_TXD2_M1/CIF_D8, 298 GMAC1_RXD0_M1/CAM_CLKOUT0, 299 GMAC1_RXD1_M1/CAM_CLKOUT1, 300 GMAC1_RXDV_CRS_M1, 301 GND25, 302 GMAC1_MCLKINOUT_M1/CIF_CLKIN, 303 CIF_CLKOUT, 304 GND54, 305 GND26, 306 USB2_HOST3_DP, 307 GMAC1_MDIO_M1/CIF_VSYNC, 308 USB2_HOST3_DM, 309 GMAC1_MDC_M1/CIF_HREF, 310 USB2_HOST2_DP, 311 GND27, 312 USB2_HOST2_DM, 313 I2C4_SCL_M0, 314 I2C4_SDA_M0, 315 GND_1, 316 GND_2

## CRYSTAL_4P
designator Y?
CLASS: IC
pins: 1, 2 GND1 (power), 3, 4 GND2 (power)

## DC-044A-20A
designator J?
footprint dc_in_th_3p_10r1x11r6
pins: 1, 2, 3, 4, 5

## DIODE
designator D?
pins: 1 K, 2 A

## DIODE BI-DIR TRIG
designator D?
footprint D0603/SMD
pins: 1, 2

## DIODE_SCHTKY
designator D?
CLASS: IC
pins: 1, 2

## FPC-24P
designator J?
pins: 1, 2, 3, 4, 5, 6, 7, 8, 9, 10, 11, 12, 13, 14, 15, 16, 17, 18, 19, 20, 21, 22, 23, 24, 25 SH1, 26 SH2

## FPC-30P
designator J?
footprint FPC-30P-0P5
pins: 1, 2, 3, 4, 5, 6, 7, 8, 9, 10, 11, 12, 13, 14, 15, 16, 17, 18, 19, 20, 21, 22, 23, 24, 25, 26, 27, 28, 29, 30, 31 SH1, 32 SH2

## FUSE
designator F?
pins: 1, 2

## HDMI-001C
designator U?
CLASS: IO; OriginalSymbolOrigin: (-200,650); Vendor: Comtek; VPN: 1166-2C105-211
footprint HDMI-SMD
pins: 1, 2, 3, 4, 5, 6, 7, 8, 9, 10, 11, 12, 13, 14, 15, 16, 17, 18, 19, G1 20, G2 21, G3 22, G4 23

## HY911130A
designator J?
pins: 1 CT, 2 TD1+, 3 TD1-, 4 RD1+, 5 TD2+, 6 TD2-, 7 RD1-, 8 RD2+, 9 RD2-, 10 CHS, 11 GRLA, 12 GRLC, 13 YELC, 14 YELA, 15 SH, 16 SH1

## IND
designator L?
CLASS: DISCRETE
pins: 1, 2

## IRM-V838M3-C/TR1
designator U?
pins: 1 GND1, 2 VCC, 3 OUT, 4 GND2

## LED
designator LED?
pins: 1 CATHODE, 2 ANODE

## LPJG0926HENL_0
designator U?, comment LPJG0926HENL
pins: 1 TD1+, 2 TD1-, 3 TD2+, 4 TD2_1, 5 TD2_2, 6 TD2-, 7 TD3+, 8 TD3-, 9 TD4+, 10 TD4-, 11 VC1, 12 VC2, 13 VC3, 14 VC4, 15 G_LED+, 16 G_LED-, 17 Y_LED+, 18 Y_LED-, 19 SHELL_GND_1, 20 SHELL_GND_2

## MAX3232CSE
designator U?
footprint 16
pins: 1 C1+, 2 V+, 3 C1-, 4 C2+, 5 C2-, 6 V-, 7 T2OUT, 8 R2IN, 9 R2OUT, 10 T2IN, 11 T1IN, 12 R1OUT, 13 R1IN, 14 T1OUT, 15 GND (power), 16 VCC (power)

## MIC_JACK
designator J?
footprint EAR_JACK
pins: 1, 2, 3, 4, 5

## MINI-PCIE
designator J?
footprint pcie_52p
pins: 1 MIC-P, 2 VBAT1, 3 MIC-N, 4 GND9, 5 SPK-P, 6 NC1, 7 SPK-N, 8 USIM-VDD, 9 GND1, 10 USIM-DATA, 11 VDD-EXT, 12 USIM-CLK, 13 RESERVED, 14 USIM-RST, 15 GND2, 16 RESERVED6, 17 RESERVED5, 18 GND10, 19 WAKEUP-IN, 20 W-DISABLE, 21 GND3, 22 PERST1, 23 UART-RXD, 24 VBAT5, 25 UART-RTS, 26 GND11, 27 GND4, 28 UART-CTS, 29 GND5, 30 UART-DCD, 31 UART-TXD, 32 WAKEUP-OUT, 33 PERST2, 34 GND12, 35 GND6, 36 USB-D-, 37 GND7, 38 USB-D+, 39 VBAT2, 40 GND13, 41 VBAT3, 42 LED-WWAN, 43 GND8, 44 USIM-PRESENCE, 45 RESERVED1, 46 UART-DTR, 47 RESERVED2, 48 NC2, 49 RESERVED3, 50 GND14, 51 RESERVED4, 52 VBAT4, 53, 54

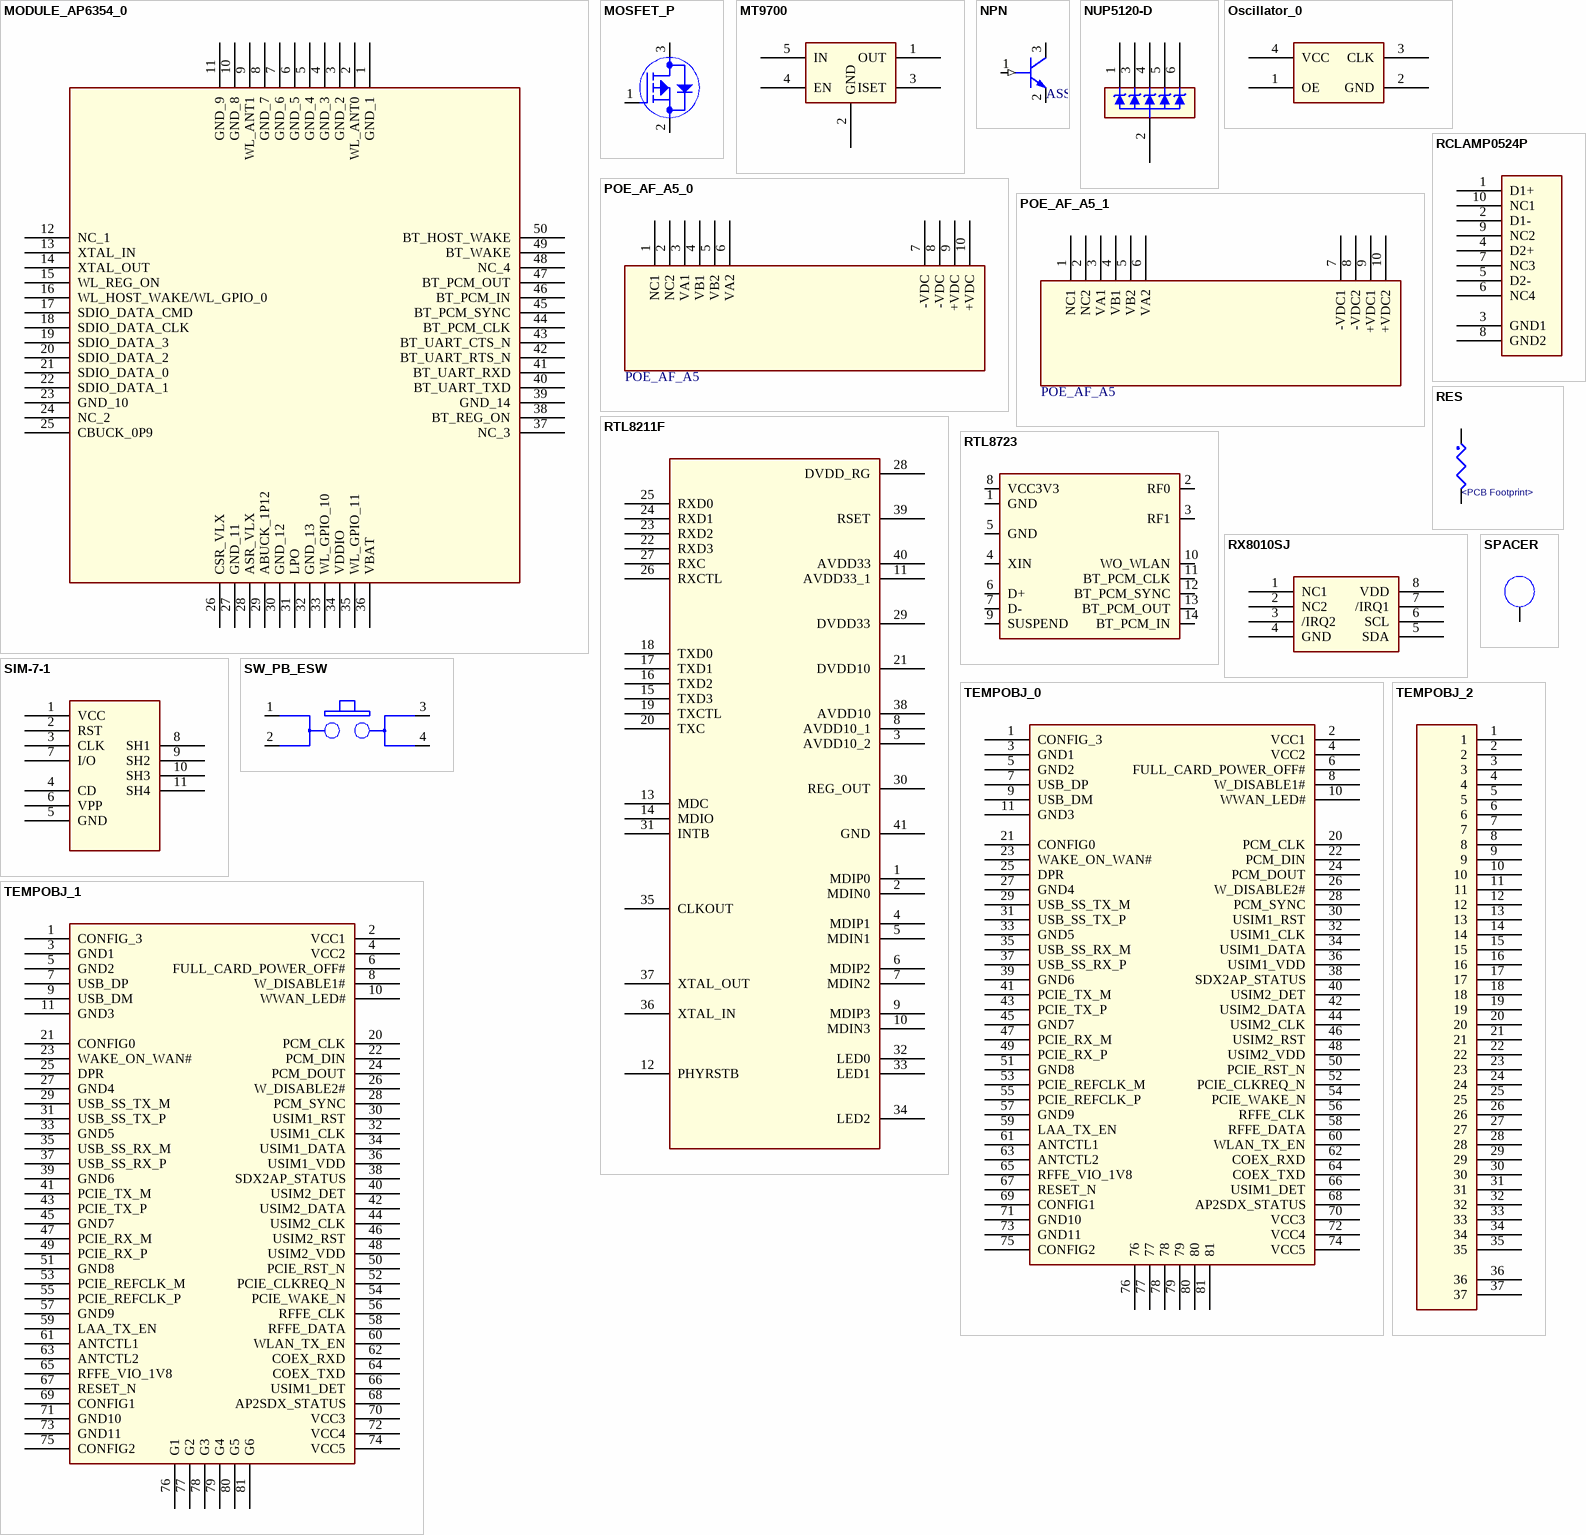
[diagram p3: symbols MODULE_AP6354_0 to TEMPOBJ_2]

## MODULE_AP6354_0
designator U?
pins: 1 GND_1, 2 WL_ANT0, 3 GND_2, 4 GND_3, 5 GND_4, 6 GND_5, 7 GND_6, 8 GND_7, 9 WL_ANT1, 10 GND_8, 11 GND_9, 12 NC_1, 13 XTAL_IN, 14 XTAL_OUT, 15 WL_REG_ON, 16 WL_HOST_WAKE/WL_GPIO_0, 17 SDIO_DATA_CMD, 18 SDIO_DATA_CLK, 19 SDIO_DATA_3, 20 SDIO_DATA_2, 21 SDIO_DATA_0, 22 SDIO_DATA_1, 23 GND_10, 24 NC_2, 25 CBUCK_0P9, 26 CSR_VLX, 27 GND_11, 28 ASR_VLX, 29 ABUCK_1P12, 30 GND_12, 31 LPO, 32 GND_13, 33 WL_GPIO_10, 34 VDDIO, 35 WL_GPIO_11, 36 VBAT, 37 NC_3, 38 BT_REG_ON, 39 GND_14, 40 BT_UART_TXD, 41 BT_UART_RXD, 42 BT_UART_RTS_N, 43 BT_UART_CTS_N, 44 BT_PCM_CLK, 45 BT_PCM_SYNC, 46 BT_PCM_IN, 47 BT_PCM_OUT, 48 NC_4, 49 BT_WAKE, 50 BT_HOST_WAKE

## MOSFET_P
designator Q?
CLASS: IC
pins: 1 GATE, 2 SOURCE, 3 DRAIN

## MT9700
designator U?
pins: 1 OUT, 2 GND, 3 ISET, 4 EN, 5 IN

## NPN
designator Q?
CLASS: IC
pins: 1 BASE (in), 2 EMITTER, 3 COLLECTOR

## NUP5120-D
designator U?
pins: 1, 2, 3, 4, 5, 6

## Oscillator_0
designator Y?
footprint 3225
pins: 1 OE, 2 GND, 3 CLK, 4 VCC

## POE_AF_A5_0
designator U?, comment POE_AF_A5
pins: 1 NC1, 2 NC2, 3 VA1, 4 VB1, 5 VB2, 6 VA2, 7 -VDC, 8 -VDC, 9 +VDC, 10 +VDC

## POE_AF_A5_1
designator U?, comment POE_AF_A5
pins: 1 NC1, 2 NC2, 3 VA1, 4 VB1, 5 VB2, 6 VA2, 7 -VDC1, 8 -VDC2, 9 +VDC1, 10 +VDC2

## RCLAMP0524P
designator U?
pins: 1 D1+, 2 D1-, 3 GND1, 4 D2+, 5 D2-, 6 NC4, 7 NC3, 8 GND2, 9 NC2, 10 NC1

## RES
designator R?  PCB Footprint: <PCB Footprint>
CLASS: DISCRETE
pins: 1, 2

## RTL8211F
designator U?
pins: 1 MDIP0, 2 MDIN0, 3 AVDD10_2, 4 MDIP1, 5 MDIN1, 6 MDIP2, 7 MDIN2, 8 AVDD10_1, 9 MDIP3, 10 MDIN3, 11 AVDD33_1, 12 PHYRSTB, 13 MDC, 14 MDIO, 15 TXD3, 16 TXD2, 17 TXD1, 18 TXD0, 19 TXCTL, 20 TXC, 21 DVDD10, 22 RXD3, 23 RXD2, 24 RXD1, 25 RXD0, 26 RXCTL, 27 RXC, 28 DVDD_RG, 29 DVDD33, 30 REG_OUT, 31 INTB, 32 LED0, 33 LED1, 34 LED2, 35 CLKOUT, 36 XTAL_IN, 37 XTAL_OUT, 38 AVDD10, 39 RSET, 40 AVDD33, 41 GND

## RTL8723
designator U?
pins: 1 GND (power), 2 RF0, 3 RF1, 4 XIN, 5 GND (power), 6 D+, 7 D-, 8 VCC3V3 (power), 9 SUSPEND, 10 WO_WLAN, 11 BT_PCM_CLK, 12 BT_PCM_SYNC, 13 BT_PCM_OUT, 14 BT_PCM_IN

## RX8010SJ
designator U?
pins: 1 NC1, 2 NC2, 3 /IRQ2, 4 GND, 5 SDA, 6 SCL, 7 /IRQ1, 8 VDD

## SIM-7-1
designator U?
pins: 1 VCC, 2 RST, 3 CLK, 4 CD, 5 GND, 6 VPP, 7 I/O, 8 SH1, 9 SH2, 10 SH3, 11 SH4

## SPACER
designator SS?
CLASS: IC
pins: 1 NC_1

## SW_PB_ESW
designator SW?
CLASS: IC
pins: 1 A1, 2 A2, 3 B1, 4 B2

## TEMPOBJ_0
designator U?
footprint M2_NGFF_B_KEY
pins: 1 CONFIG_3, 2 VCC1, 3 GND1, 4 VCC2, 5 GND2, 6 FULL_CARD_POWER_OFF#, 7 USB_DP, 8 W_DISABLE1#, 9 USB_DM, 10 WWAN_LED#, 11 GND3, 20 PCM_CLK, 21 CONFIG0, 22 PCM_DIN, 23 WAKE_ON_WAN#, 24 PCM_DOUT, 25 DPR, 26 W_DISABLE2#, 27 GND4, 28 PCM_SYNC, 29 USB_SS_TX_M, 30 USIM1_RST, 31 USB_SS_TX_P, 32 USIM1_CLK, 33 GND5, 34 USIM1_DATA, 35 USB_SS_RX_M, 36 USIM1_VDD, 37 USB_SS_RX_P, 38 SDX2AP_STATUS, 39 GND6, 40 USIM2_DET, 41 PCIE_TX_M, 42 USIM2_DATA, 43 PCIE_TX_P, 44 USIM2_CLK, 45 GND7, 46 USIM2_RST, 47 PCIE_RX_M, 48 USIM2_VDD, 49 PCIE_RX_P, 50 PCIE_RST_N, 51 GND8, 52 PCIE_CLKREQ_N, 53 PCIE_REFCLK_M, 54 PCIE_WAKE_N, 55 PCIE_REFCLK_P, 56 RFFE_CLK, 57 GND9, 58 RFFE_DATA, 59 LAA_TX_EN, 60 WLAN_TX_EN, 61 ANTCTL1, 62 COEX_RXD, 63 ANTCTL2, 64 COEX_TXD, 65 RFFE_VIO_1V8, 66 USIM1_DET, 67 RESET_N, 68 AP2SDX_STATUS, 69 CONFIG1, 70 VCC3, 71 GND10, 72 VCC4, 73 GND11, 74 VCC5, 75 CONFIG2, 76, 77, 78, 79, 80, 81

## TEMPOBJ_1
designator U?
footprint M2_NGFF_B_KEY
pins: 1 CONFIG_3, 2 VCC1, 3 GND1, 4 VCC2, 5 GND2, 6 FULL_CARD_POWER_OFF#, 7 USB_DP, 8 W_DISABLE1#, 9 USB_DM, 10 WWAN_LED#, 11 GND3, 20 PCM_CLK, 21 CONFIG0, 22 PCM_DIN, 23 WAKE_ON_WAN#, 24 PCM_DOUT, 25 DPR, 26 W_DISABLE2#, 27 GND4, 28 PCM_SYNC, 29 USB_SS_TX_M, 30 USIM1_RST, 31 USB_SS_TX_P, 32 USIM1_CLK, 33 GND5, 34 USIM1_DATA, 35 USB_SS_RX_M, 36 USIM1_VDD, 37 USB_SS_RX_P, 38 SDX2AP_STATUS, 39 GND6, 40 USIM2_DET, 41 PCIE_TX_M, 42 USIM2_DATA, 43 PCIE_TX_P, 44 USIM2_CLK, 45 GND7, 46 USIM2_RST, 47 PCIE_RX_M, 48 USIM2_VDD, 49 PCIE_RX_P, 50 PCIE_RST_N, 51 GND8, 52 PCIE_CLKREQ_N, 53 PCIE_REFCLK_M, 54 PCIE_WAKE_N, 55 PCIE_REFCLK_P, 56 RFFE_CLK, 57 GND9, 58 RFFE_DATA, 59 LAA_TX_EN, 60 WLAN_TX_EN, 61 ANTCTL1, 62 COEX_RXD, 63 ANTCTL2, 64 COEX_TXD, 65 RFFE_VIO_1V8, 66 USIM1_DET, 67 RESET_N, 68 AP2SDX_STATUS, 69 CONFIG1, 70 VCC3, 71 GND10, 72 VCC4, 73 GND11, 74 VCC5, 75 CONFIG2, 76 G1, 77 G2, 78 G3, 79 G4, 80 G5, 81 G6

## TEMPOBJ_2
designator J?
footprint FPC-30P-0P5
pins: 1, 2, 3, 4, 5, 6, 7, 8, 9, 10, 11, 12, 13, 14, 15, 16, 17, 18, 19, 20, 21, 22, 23, 24, 25, 26, 27, 28, 29, 30, 31, 32, 33, 34, 35, 36, 37

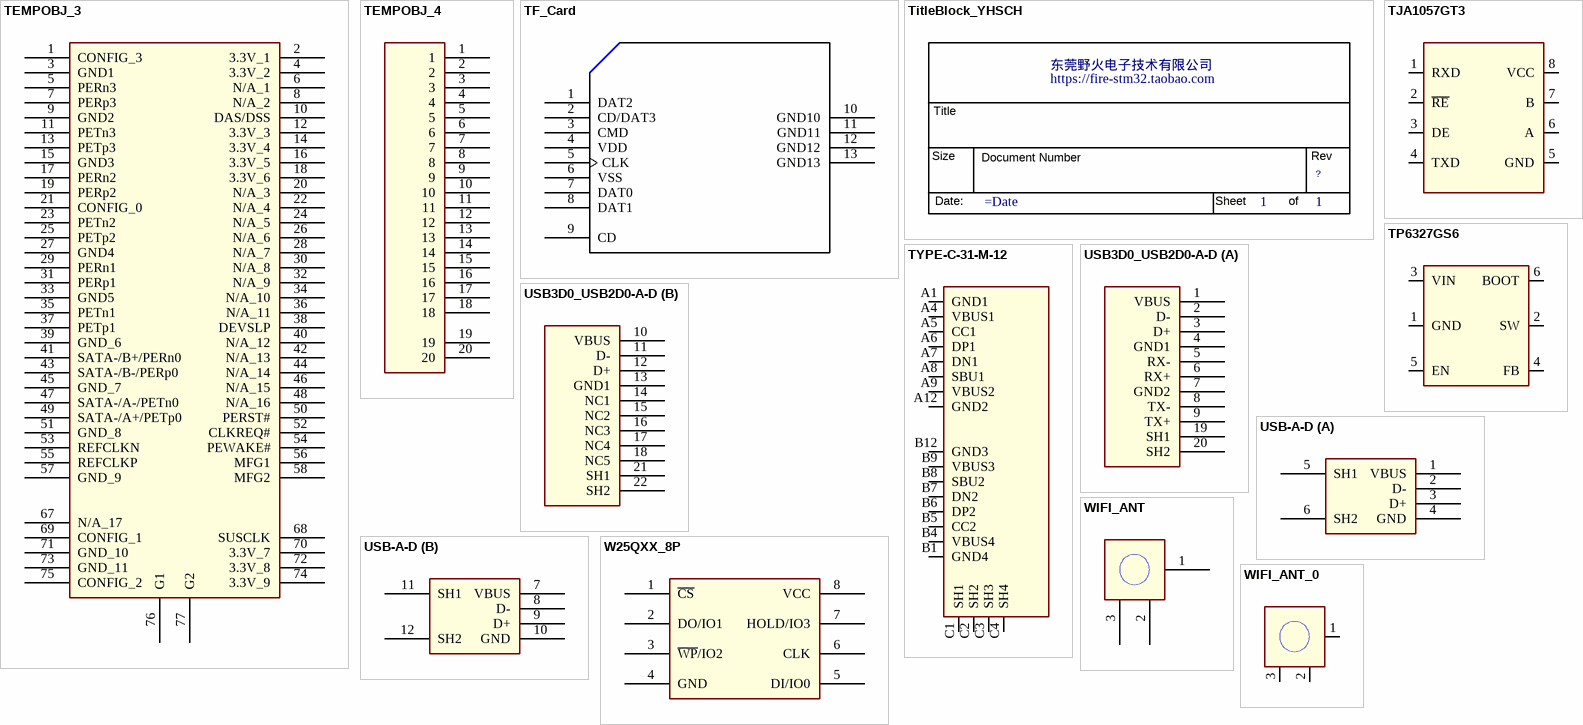
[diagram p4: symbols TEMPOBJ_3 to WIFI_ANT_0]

## TEMPOBJ_3
designator J?
footprint M2_NGFF_M_KEY
pins: 1 CONFIG_3, 2 3.3V_1, 3 GND1, 4 3.3V_2, 5 PERn3, 6 N/A_1, 7 PERp3, 8 N/A_2, 9 GND2, 10 DAS/DSS, 11 PETn3, 12 3.3V_3, 13 PETp3, 14 3.3V_4, 15 GND3, 16 3.3V_5, 17 PERn2, 18 3.3V_6, 19 PERp2, 20 N/A_3, 21 CONFIG_0, 22 N/A_4, 23 PETn2, 24 N/A_5, 25 PETp2, 26 N/A_6, 27 GND4, 28 N/A_7, 29 PERn1, 30 N/A_8, 31 PERp1, 32 N/A_9, 33 GND5, 34 N/A_10, 35 PETn1, 36 N/A_11, 37 PETp1, 38 DEVSLP, 39 GND_6, 40 N/A_12, 41 SATA-/B+/PERn0, 42 N/A_13, 43 SATA-/B-/PERp0, 44 N/A_14, 45 GND_7, 46 N/A_15, 47 SATA-/A-/PETn0, 48 N/A_16, 49 SATA-/A+/PETp0, 50 PERST#, 51 GND_8, 52 CLKREQ#, 53 REFCLKN, 54 PEWAKE#, 55 REFCLKP, 56 MFG1, 57 GND_9, 58 MFG2, 67 N/A_17, 68 SUSCLK, 69 CONFIG_1, 70 3.3V_7, 71 GND_10, 72 3.3V_8, 73 GND_11, 74 3.3V_9, 75 CONFIG_2, 76 G1, 77 G2

## TEMPOBJ_4
designator J?
footprint FPC-18P-0P5
pins: 1, 2, 3, 4, 5, 6, 7, 8, 9, 10, 11, 12, 13, 14, 15, 16, 17, 18, 19, 20

## TF_Card
designator J?
CLASS: IO
pins: 1 DAT2, 2 CD/DAT3, 3 CMD, 4 VDD (power), 5 CLK, 6 VSS (power), 7 DAT0, 8 DAT1, 9 CD, 10 GND10, 11 GND11, 12 GND12, 13 GND13

## TitleBlock_YHSCH
designator *  OrgName: 东莞野火电子技术有限公司  Page Number: 1  (hidden comment: *)  (graphical)

## TJA1057GT3
designator U?
CLASS: IC
pins: 1 RXD, 2 ~{RE}, 3 DE, 4 TXD, 5 GND, 6 A, 7 B, 8 VCC

## TP6327GS6
designator U?
pins: 1 GND, 2 SW, 3 VIN, 4 FB, 5 EN, 6 BOOT

## TYPE-C-31-M-12
designator J?
footprint TYPE-C-31-M-12
pins: A1 GND1, A4 VBUS1, A5 CC1, A6 DP1, A7 DN1, A8 SBU1, A9 VBUS2, A12 GND2, B1 GND4, B4 VBUS4, B5 CC2, B6 DP2, B7 DN2, B8 SBU2, B9 VBUS3, B12 GND3, C1 SH1, C2 SH2, C3 SH3, C4 SH4

## USB3D0_USB2D0-A-D
designator J?
footprint USB3D0-AF-18P
part A pins: 1 VBUS, 2 D-, 3 D+, 4 GND1, 5 RX-, 6 RX+, 7 GND2, 8 TX-, 9 TX+, 19 SH1, 20 SH2
part B pins: 10 VBUS, 11 D-, 12 D+, 13 GND1, 14 NC1, 15 NC2, 16 NC3, 17 NC4, 18 NC5, 21 SH1, 22 SH2

## USB-A-D
designator J?
footprint USB-A-D
part A pins: 1 VBUS, 2 D-, 3 D+, 4 GND, 5 SH1, 6 SH2
part B pins: 7 VBUS, 8 D-, 9 D+, 10 GND, 11 SH1, 12 SH2

## W25QXX_8P
designator U?
pins: 1 ~{CS}, 2 DO/IO1, 3 ~{WP}/IO2, 4 GND, 5 DI/IO0, 6 CLK, 7 HOLD/IO3, 8 VCC

## WIFI_ANT
designator CN?
footprint UFL-3
pins: 1, 2, 3

## WIFI_ANT_0
designator CN?
footprint UFL-3
pins: 1, 2, 3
